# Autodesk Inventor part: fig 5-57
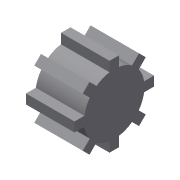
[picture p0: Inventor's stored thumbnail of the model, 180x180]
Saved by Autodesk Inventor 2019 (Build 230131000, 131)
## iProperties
Created: 2005-12
Part Number: fig 5-57
Document SubType Name: Modeling
Designer: CADCIM
Density: 1 g/cm^3
Material: Generic
Appearance: Default
Author: CADCIM
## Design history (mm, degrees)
sketch "Sketch1"
  geometry: C1 r 27.506 at (0, 0)
  constraints: 1 centre point
extrude "Extrusion1" new body sketch "Sketch1" distance "d0" = 20; taper "d1" = 0 deg
sketch "Sketch2"
  geometry: L1 (-12.302, -1.705)-(-16.396, -1.705); L2 (-16.396, -1.705)-(-16.396, 2.216); L3 (-16.396, 2.216)-(-12.302, 2.216); L4 (-7.311, -9.833)-(-10.206, -12.728); L5 (-10.206, -12.728)-(-12.979, -9.955); L6 (-12.979, -9.955)-(-10.084, -7.06); L7 (1.966, -12.051)-(1.966, -16.145); L8 (1.966, -16.145)-(-1.956, -16.145); L9 (-1.956, -16.145)-(-1.956, -12.051); L10 (10.093, -7.06)-(12.988, -9.955); L11 (12.988, -9.955)-(10.215, -12.728); L12 (10.215, -12.728)-(7.32, -9.833); L13 (12.311, 2.216)-(16.405, 2.216); L14 (16.405, 2.216)-(16.405, -1.705); L15 (16.405, -1.705)-(12.311, -1.705); L16 (7.32, 10.344)-(10.215, 13.239); L17 (10.215, 13.239)-(12.988, 10.466); L18 (12.988, 10.466)-(10.093, 7.571); L19 (-1.956, 12.562)-(-1.956, 16.656); L20 (-1.956, 16.656)-(1.966, 16.656); L21 (1.966, 16.656)-(1.966, 12.562); L22 (-10.084, 7.571)-(-12.979, 10.466); L23 (-12.979, 10.466)-(-10.206, 13.239); L24 (-10.206, 13.239)-(-7.311, 10.344); A1 r 12.462 centre (0.005, 0.256) between (-12.302, -1.705) and (-10.084, -7.06); A2 r 12.462 centre (0.005, 0.256) between (-7.311, -9.833) and (-1.956, -12.051); A3 r 12.462 centre (0.005, 0.256) between (1.966, -12.051) and (7.32, -9.833); A4 r 12.462 centre (0.005, 0.256) between (10.093, -7.06) and (12.311, -1.705); A5 r 12.462 centre (0.005, 0.256) between (12.311, 2.216) and (10.093, 7.571); A6 r 12.462 centre (0.005, 0.256) between (7.32, 10.344) and (1.966, 12.562); A7 r 12.462 centre (0.005, 0.256) between (-1.956, 12.562) and (-7.311, 10.344); A8 r 12.462 centre (0.005, 0.256) between (-10.084, 7.571) and (-12.302, 2.216)
  constraints: 48 end point, 16 point on circle, 8 centre point, 2 parallel, 1 horizontal, 1 perpendicular, 57 other
  dimensions: "d4" = 360 deg dimension on A1.centre L2.end (derived)
extrude "Extrusion2" sketch "Sketch2" distance "d6" = 20; taper "d7" = 0 deg
body "Solid1"
